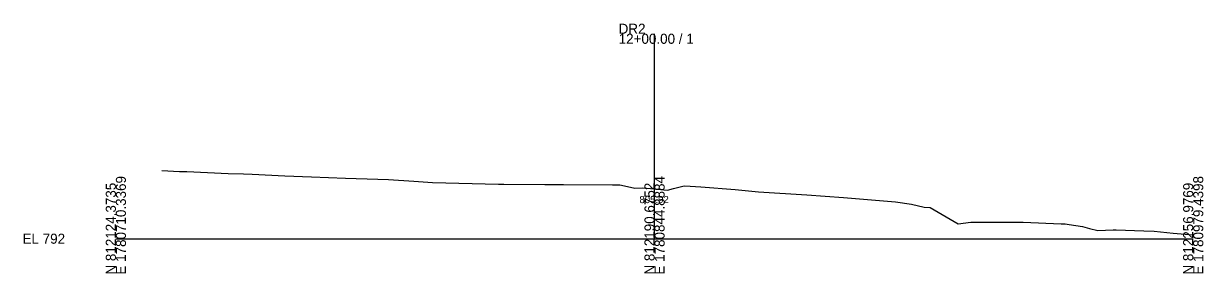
# Model space of a CAD drawing. Extents: x -26 to 303, y -10 to 2560.
# Drawn here: x -25.7 to 302.8, y 2490.3 to 2560 of the extents above; entities that cross this region are included whole.
import ezdxf

# ---------------------------------------------------------------- set-up
doc = ezdxf.new("R2010")
doc.units = 0
for name, color, linetype in [('Exist Cross Section Cell', 7, 'Continuous'), ('Exist XS Center Line Elevation Label', 7, 'Continuous'), ('Exist XS Ground Line', 7, 'Continuous')]:
    doc.layers.add(name, color=color, linetype=linetype)

msp = doc.modelspace()

# ---------------------------------------------------------------- linework, layer by layer
at = {"layer": 'Exist Cross Section Cell'}
for p, q in [((150, 2500), (150, 2557.18)), ((0, 2500), (150, 2500)), ((150, 2500), (300, 2500))]:
    msp.add_line(p, q, dxfattribs=at)
at = {"layer": 'Exist XS Ground Line'}
for p, q in [((12.78, 2519.06), (17.71, 2518.75)), ((17.71, 2518.75), (19.75, 2518.73)), ((19.75, 2518.73), (31.23, 2518.19)), ((31.23, 2518.19), (35.54, 2518.12)), ((35.54, 2518.12), (37.91, 2517.97)), ((37.91, 2517.97), (47.05, 2517.56)), ((47.05, 2517.56), (54.5, 2517.24)), ((54.5, 2517.24), (63.96, 2516.9)), ((63.96, 2516.9), (72.95, 2516.59)), ((72.95, 2516.59), (75.91, 2516.48)), ((75.91, 2516.48), (82.96, 2516.01)), ((82.96, 2516.01), (88.15, 2515.68)), ((88.15, 2515.68), (106.54, 2515.26)), ((106.54, 2515.26), (108.08, 2515.25)), ((108.08, 2515.25), (119.49, 2515.12)), ((119.49, 2515.12), (124.35, 2515.08)), ((124.35, 2515.08), (124.67, 2515.08)), ((124.67, 2515.08), (138.33, 2514.99)), ((138.33, 2514.99), (140.34, 2514.99)), ((140.34, 2514.99), (144.1, 2514.2)), ((144.1, 2514.2), (144.56, 2514.13)), ((144.56, 2514.13), (146.66, 2514.23)), ((146.66, 2514.23), (150, 2513.92)), ((150, 2513.92), (152.62, 2513.68)), ((152.62, 2513.68), (153.57, 2513.58)), ((153.57, 2513.58), (155.3, 2514.05)), ((155.3, 2514.05), (158.23, 2514.76)), ((158.23, 2514.76), (159.91, 2514.68)), ((159.91, 2514.68), (162.93, 2514.47)), ((162.93, 2514.47), (172.45, 2513.72)), ((172.45, 2513.72), (176.13, 2513.39)), ((176.13, 2513.39), (178.94, 2513.11)), ((178.94, 2513.11), (192.45, 2512.24)), ((192.45, 2512.24), (202.61, 2511.52)), ((202.61, 2511.52), (217.11, 2510.33)), ((217.11, 2510.33), (221.56, 2509.66)), ((221.56, 2509.66), (225.08, 2508.83)), ((225.08, 2508.83), (226.73, 2508.68)), ((226.73, 2508.68), (234.57, 2504.17)), ((234.57, 2504.17), (238.1, 2504.65)), ((238.1, 2504.65), (240.54, 2504.65)), ((240.54, 2504.65), (241.41, 2504.63)), ((241.41, 2504.63), (248.74, 2504.61)), ((248.74, 2504.61), (252.63, 2504.59)), ((252.63, 2504.59), (263.2, 2504.15)), ((263.2, 2504.15), (264.32, 2504.11)), ((264.32, 2504.11), (265.42, 2503.93)), ((265.42, 2503.93), (269.14, 2503.42)), ((269.14, 2503.42), (271.11, 2502.87)), ((271.11, 2502.87), (273.4, 2502.25)), ((273.4, 2502.25), (277.7, 2502.5)), ((277.7, 2502.5), (278.57, 2502.46)), ((278.57, 2502.46), (286.25, 2502.16)), ((286.25, 2502.16), (289.11, 2502.06)), ((289.11, 2502.06), (294.44, 2501.59)), ((294.44, 2501.59), (300, 2501.07))]:
    msp.add_line(p, q, dxfattribs=at)

# ---------------------------------------------------------------- texts
at = {"layer": 'Exist Cross Section Cell'}
for s, p in [('DR2', (140, 2557.18)), ('12+00.00 / 1', (140, 2554.38)), ('EL 792', (-26, 2498.6))]:
    msp.add_text(s, height=2.8, dxfattribs=at).set_placement(p)
for s, p in [('E 1780710.3369', (2.8, 2490)), ('E 1780844.8884', (152.8, 2490)), ('E 1780979.4398', (302.8, 2490)), ('N 812124.3735', (0, 2490)), ('N 812190.6752', (150, 2490)), ('N 812256.9769', (300, 2490))]:
    msp.add_text(s, height=2.8, rotation=90, dxfattribs=at).set_placement(p)
at = {"layer": 'Exist XS Center Line Elevation Label'}
msp.add_text('805.92', height=2, dxfattribs=at).set_placement((145.79, 2509.92))

doc.saveas('drawing.dxf')
